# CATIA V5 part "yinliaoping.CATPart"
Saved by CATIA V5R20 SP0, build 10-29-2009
Part number: Part1
Material "DS Light Blue": density 7860 kg/m3, Young's modulus 2e+11 Pa, Poisson ratio 0.266
Bounding box of the stored display mesh (mm): x -25 to 25, y -25 to 477.831, z 0 to 569.591
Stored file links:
  C:\Users\ysz\Desktop\新建文件夹 (2)\yinliaoping.CATPart
  D:\CATIAR20\win_b64\startup\materials\Catalog.CATMaterial
  D:\CATIAR20\win_b64\startup\materials\floor.jpg
  D:\CATIAR20\win_b64\startup\materials\blue_fabric_02.jpg
  D:\CATIAR20\win_b64\startup\materials\blue_env_512x512.jpg
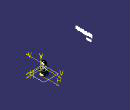
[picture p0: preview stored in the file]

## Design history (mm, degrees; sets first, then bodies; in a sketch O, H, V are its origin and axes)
Set1
  Sketch1 on xy-plane, origin (0, 0, 0), H (1, 0, 0), V (0, 1, 0)
    line L1 (25, 25) -> (25, -25)
    line L2 (25, -25) -> (-25, -25)
    line L3 (-25, -25) -> (-25, 25)
    line L4 (-25, 25) -> (25, 25)
    length L1 = 50
    length L4 = 50
    vertical: L1 V, L3 V
    horizontal: L2 H, L4 H
    equidistance: L1 L3 O, L2 L4 O
  Sketch2 on face of Pad1 from Sketch1.L1, origin (25, 0, 0), H (0, 1, 0), V (0, 0, 1)
    spline S1 through (-37.2016, 14.3943) (-10.1792, 27.927) (7.291, 18.0281) (38.3353, 27.927)
  Extrude1: Element1 Sketch2, Lim1 53, Lim2 53
Body1 (main body), material "DS Light Blue"
  Pad1: profile Sketch1, direction (0, 0, 1), length 50
  Fillet1: on edge [face of Pad1 from Sketch1.L4 | face of Pad1 from Sketch1.L1]; edge [face of Pad1 from Sketch1.L1 | face of Pad1 from Sketch1.L2]; edge [face of Pad1 from Sketch1.L2 | face of Pad1 from Sketch1.L3]; edge [face of Pad1 from Sketch1.L3 | face of Pad1 from Sketch1.L4]
  Plane1: type Offset, RefPlane xy-plane, Offset 80
  Sketch3 on Plane1, origin (0, 0, 80), H (1, 0, 0), V (0, 1, 0)
    circle A1 centre (0, 0) radius 15
    radius A1 = 15
  Pad2: profile Sketch3, direction (0, 0, 1), length 20
  Sketch4 on end face of Pad1, origin (0, 0, 50), H (1, 0, 0), V (0, 1, 0)
    point P1 (25, 0)
    distance P1 O = 25
    coincidence: P1 H
  Sketch5 on start face of Pad2, origin (0, 0, 80), H (1, 0, 0), V (0, -1, 0)
    point P1 (15, 0)
    distance P1 O = 15
    coincidence: P1 H
  Sketch6 on end face of Pad1, origin (0, 0, 50), H (1, 0, 0), V (0, 1, 0)
    point P1 (0, 0)
    point P2 (0, 25)
    distance P2 P1 = 25
    coincidence: P1 O, P2 V
  Loft1: solid, Sections ({boundary Boundary {extract ExtractElem end face of Pad1}}; {boundary Boundary {extract ExtractElem start face of Pad2}}), StartFace end face of Pad1, EndFace start face of Pad2
  MultiSel1: CommonCtxFeats ({extract ExtractElem face of Pad1 from Sketch1.L2}; {extract ExtractElem face of Fillet1}; {extract ExtractElem face of Pad1 from Sketch1.L1}; {extract ExtractElem face of Fillet1}; {extract ExtractElem face of Pad1 from Sketch1.L4}; {extract ExtractElem face of Fillet1}; {extract ExtractElem face of Pad1 from Sketch1.L3}; {extract ExtractElem face of Fillet1})
  Sketch7 on face of Pad1 from Sketch1.L3, origin (-25, 0, 0), H (0, -1, 0), V (0, 0, 1)
    spline S1 through (-38.912, 44.8124) (-17.3383, 31.002) (-3.0315, 36.8884) (13.7046, 42.9633) (37.1637, 32.134) (41.9327, 26.2476)
  Extrude2: Element1 Sketch7, Lim1 55, Lim2 55
  MultiSel2: CommonCtxFeats ({extract ExtractElem face of Pad1 from Sketch1.L2}; {extract ExtractElem face of Fillet1}; {extract ExtractElem face of Pad1 from Sketch1.L1}; {extract ExtractElem face of Fillet1}; {extract ExtractElem face of Pad1 from Sketch1.L4}; {extract ExtractElem face of Fillet1}; {extract ExtractElem face of Pad1 from Sketch1.L3}; {extract ExtractElem face of Fillet1})
  Join1: Elements ({intersect ToIntersect1 {extract ExtractElem face of Pad1 from Sketch1.L2}, ToIntersect2 Extrude2}; {intersect ToIntersect1 {extract ExtractElem face of Pad1 from Sketch1.L1}, ToIntersect2 Extrude2}; {intersect ToIntersect1 {extract ExtractElem face of Fillet1}, ToIntersect2 Extrude2}; {intersect ToIntersect1 {extract ExtractElem face of Pad1 from Sketch1.L4}, ToIntersect2 Extrude2}; {intersect ToIntersect1 {extract ExtractElem face of Fillet1}, ToIntersect2 Extrude2}; {intersect ToIntersect1 {extract ExtractElem face of Pad1 from Sketch1.L3}, ToIntersect2 Extrude2}; {intersect ToIntersect1 {extract ExtractElem face of Fillet1}, ToIntersect2 Extrude2}; {intersect ToIntersect1 {extract ExtractElem face of Fillet1}, ToIntersect2 Extrude2})
  Join2: Elements ({intersect ToIntersect1 {extract ExtractElem face of Pad1 from Sketch1.L1}, ToIntersect2 Extrude1}; {intersect ToIntersect1 {extract ExtractElem face of Fillet1}, ToIntersect2 Extrude1}; {intersect ToIntersect1 {extract ExtractElem face of Pad1 from Sketch1.L4}, ToIntersect2 Extrude1}; {intersect ToIntersect1 {extract ExtractElem face of Fillet1}, ToIntersect2 Extrude1}; {intersect ToIntersect1 {extract ExtractElem face of Pad1 from Sketch1.L3}, ToIntersect2 Extrude1}; {intersect ToIntersect1 {extract ExtractElem face of Fillet1}, ToIntersect2 Extrude1}; {intersect ToIntersect1 {extract ExtractElem face of Pad1 from Sketch1.L2}, ToIntersect2 Extrude1}; {intersect ToIntersect1 {extract ExtractElem face of Fillet1}, ToIntersect2 Extrude1})
  Plane2: type Normal, Curve Join1, RefPoint vertex [face of MultiSel2 | face of MultiSel2]
  Circle1: type CtrRad, Start 0, End 180, Center vertex [face of MultiSel2 | face of MultiSel2], Support Plane2, Radius 1, FirstDirection (0, 1, 0)
  Plane3: type Normal, Curve Join2, RefPoint vertex [face of MultiSel1 | face of MultiSel1]
  Circle2: type CtrRad, Start 0, End 180, Center vertex [face of MultiSel1 | face of MultiSel1], Support Plane3, Radius 1, FirstDirection (0, -1, 0)
  Slot1: profile Circle1, centre curve Join1
  Slot2: profile Circle2, centre curve Join2
  Shell1: IntOffset 1, Face end face of Pad2, ExtOffset 0
  Point1: type OnSurface, Support face of Pad2 from Sketch3.A1, Length 8, Direction (-0.0374, 0.0003, -0.9993)
  Helix1: Direction Z axis, RefPoint Point1, Pitch 3, Height 16, TaperAngle 0
  Point2: type OnCurve, Support Helix1, Length 5
  Point3: type OnCurve, Support Helix1, RefPoint vertex of Helix1, Length -5
  Line1: type PtDir, RefPoint vertex of Helix1, Direction (1, 0, 0), Start 0, End 5
  Line2: type PtDir, RefPoint Point1, Direction (0, 1, 0), Start 0, End 5
  Connect1: Curve1 Line1, Point1 vertex of Line1, Tension1 1, Curve2 Helix1, Point2 Point3, Tension2 1
  Connect2: Curve1 Line2, Point1 vertex of Line2, Tension1 1, Curve2 Connect1, Point2 Point2, Tension2 1
  Plane4: type Normal, Curve Connect2, RefPoint vertex of Connect1
  Circle3: type CtrRad, Start 0, End 180, Center vertex of Connect1, Support Plane4, Radius 1, FirstDirection (0, 1, 0)
  Rib1: profile Circle3, centre curve Connect2
  Body2
    Sketch8 on {extract ExtractElem start face of Pad2}, origin (0, 0, 80), H (1, 0, 0), V (0, 1, 0)
      circle A1 centre (0, 0) radius 14
      radius A1 = 14
    Pad3: profile Sketch8, direction (0, 0, 1), length 20
  Remove1: tool Body2
Body3
  Sketch9 on face of Pad1 from Sketch1.L1, origin (25, 0, 0), H (0, 1, 0), V (0, 0, 1)
    polyline C1
    polyline C2
    polyline C3
    polyline C4
    polyline C5
    polyline C6
    polyline C7
    polyline C8
    polyline C9
    polyline C10
    polyline C11
    polyline C12
    polyline C13
    polyline C14
    polyline C15
    polyline C16
    polyline C17
    polyline C18
    polyline C19
    polyline C20
    polyline C21
    polyline C22
    polyline C23
    polyline C24
    polyline C25
    polyline C26
    polyline C27
    polyline C28
    polyline C29
    polyline C30
    polyline C31
    polyline C32
    polyline C33
  Sketch10 on face of Pad1 from Sketch1.L1, origin (25, 0, 0), H (0, 1, 0), V (0, 0, 1)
